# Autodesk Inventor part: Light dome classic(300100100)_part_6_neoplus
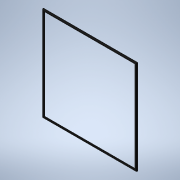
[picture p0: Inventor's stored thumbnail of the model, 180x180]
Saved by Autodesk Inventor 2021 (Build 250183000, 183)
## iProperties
Created: 2026-04
Part Number: Light dome classic(300100100)_part_6_neoplus
Material: Generic
Catalog Web Link: www.3dfindit.com
Description: Light dome classic_part_6_neoplus-
Vendor: KINGSPAN
Document SubType Name: Modeling
Designer: psAdmin
Manufacturer: KINGSPAN
Mass: 667.294 g
Surface Area: 1846.83 cm^2
Volume: 667.294 cm^3
Density: 1 g/cm^3
Appearance: PSOLRGB-128-128-128
Category: PARTsolutions
Company: KINGSPAN
Title: Light dome classic(300100100)_part_6_neoplus
Author: Cadenas PARTsolutions
PSOL_IDENT_0: {$CADENAS_DATA/23d-libs/kingspan_kla/light_dome_classic_neoplus/parts/part_6.prj},268 {VTYP=3D},{NB=
PSOL_IDENT_1: Light dome classic(300100100)_part_6_neoplus},{LINA=Light dome classic(300100100)_part_6_neoplus},{N
PSOL_IDENT_2: N=Light dome classic_part_6_neoplus},{DATE=20.03.2025 09:30:52},{GEOMDATE=27.10.2022 10:10:00},{VERS
PSOL_IDENT_3: ION=},{LINEID=10},{WBVAR=LODLEVEL,L,W},{WBNUMERIC=W}  {NB=Light dome classic(300100100)_part_6_neopl
PSOL_IDENT_4: us},{LINA=Light dome classic(300100100)_part_6_neoplus},{KT=DUMMY},{IDNR=},{PN=Light dome classic},{
PSOL_IDENT_5: LODLEVEL=300},{L=100},{W=100},{WX=100,150,200,250,300},{LX=1000},{XWX=1000}
NB: Light dome classic(300100100)_part_6_neoplus
NN: Light dome classic_part_6_neoplus
NBSYN: $PN.($LODLEVEL.$L.$W.)_part_6_neoplus
LINA: Light dome classic(300100100)_part_6_neoplus
CATALOG: Light + Air
PN: Light dome classic
LODLEVEL: 300
L: 100
W: 100
SUPPLIER: KINGSPAN
ARTICLENO: Light dome classic(300100100)_part_6_neoplus
BOMINFO: Light dome classic(300100100)_part_6_neoplus
CREATOR: CADENAS GmbH
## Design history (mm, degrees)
sketch "Sketch_1"
  geometry: L1 (-423.235, 17.946)-(-433.911, 17.946); L2 (-435.365, 1.946)-(-426.535, 1.946); L3 (-424.735, 12.349)-(-423.235, 17.946); A1 r 12.5 centre (-425.1, 9.079) between (-433.911, 17.946) and (-435.365, 1.946); A2 r 12.5 centre (-436.8, 9.079) between (-426.535, 1.946) and (-424.735, 12.349)
  constraints: 6 end point, 4 point on circle, 2 centre point
extrude "Extrusion1" join sketch "Sketch_1" stored distance "d0" = 2000; taper "d1" = 0 deg
sketch "Sketch_2"
  geometry: L1 (423.235, 17.946)-(424.735, 12.349); L2 (426.535, 1.946)-(435.365, 1.946); L3 (433.911, 17.946)-(423.235, 17.946); A1 r 12.5 centre (436.8, 9.079) between (424.735, 12.349) and (426.535, 1.946); A2 r 12.5 centre (425.1, 9.079) between (435.365, 1.946) and (433.911, 17.946)
  constraints: 6 end point, 4 point on circle, 2 centre point
extrude "Extrusion2" join sketch "Sketch_2" stored distance "d2" = 2000; taper "d3" = 0 deg
sketch "Sketch_3"
  geometry: L1 (433.911, 17.946)-(423.235, 17.946); L2 (423.235, 17.946)-(424.735, 12.349); L3 (426.535, 1.946)-(435.365, 1.946); A1 r 12.5 centre (425.1, 9.079) between (435.365, 1.946) and (433.911, 17.946); A2 r 12.5 centre (436.8, 9.079) between (424.735, 12.349) and (426.535, 1.946)
  constraints: 6 end point, 4 point on circle, 2 centre point
extrude "Extrusion3" join sketch "Sketch_3" stored distance "d4" = 2000; taper "d5" = 0 deg
sketch "Sketch_4"
  geometry: L1 (-423.235, 17.946)-(-433.911, 17.946); L2 (-435.365, 1.946)-(-426.535, 1.946); L3 (-424.735, 12.349)-(-423.235, 17.946); A1 r 12.5 centre (-425.1, 9.079) between (-433.911, 17.946) and (-435.365, 1.946); A2 r 12.5 centre (-436.8, 9.079) between (-426.535, 1.946) and (-424.735, 12.349)
  constraints: 6 end point, 4 point on circle, 2 centre point
extrude "Extrusion4" join sketch "Sketch_4" stored distance "d6" = 2000; taper "d7" = 0 deg
sketch "Sketch_5"
  geometry: L1 (-429.25, 37.946)-(-1000, 37.946); L2 (-1000, 37.946)-(-1000, -12.054); L3 (-1000, -12.054)-(-436.988, -12.054); L4 (-436.988, -12.054)-(-436.988, 5.216); L5 (-433.911, 17.946)-(-429.25, 17.946); L6 (-429.25, 17.946)-(-429.25, 37.946); A1 r 12.5 centre (-425.1, 9.079) between (-433.911, 17.946) and (-436.988, 5.216)
  constraints: 12 end point, 2 point on circle, 1 centre point
extrude "Extrusion5" cut sketch "Sketch_5" stored distance "d8" = 2000; taper "d9" = 0 deg
sketch "Sketch_6"
  geometry: L1 (1000, -12.054)-(1000, 37.946); L2 (1000, 37.946)-(429.25, 37.946); L3 (429.25, 37.946)-(429.25, 17.946); L4 (429.25, 17.946)-(433.911, 17.946); L5 (436.988, 5.216)-(436.988, -12.054); L6 (436.988, -12.054)-(1000, -12.054); A1 r 12.5 centre (425.1, 9.079) between (436.988, 5.216) and (433.911, 17.946)
  constraints: 12 end point, 2 point on circle, 1 centre point
extrude "Extrusion6" cut sketch "Sketch_6" stored distance "d10" = 2000; taper "d11" = 0 deg
sketch "Sketch_7"
  geometry: L1 (1000, 37.946)-(429.25, 37.946); L2 (429.25, 37.946)-(429.25, 17.946); L3 (429.25, 17.946)-(433.911, 17.946); L4 (436.988, 5.216)-(436.988, -12.054); L5 (436.988, -12.054)-(1000, -12.054); L6 (1000, -12.054)-(1000, 37.946); A1 r 12.5 centre (425.1, 9.079) between (436.988, 5.216) and (433.911, 17.946)
  constraints: 12 end point, 2 point on circle, 1 centre point
extrude "Extrusion7" cut sketch "Sketch_7" stored distance "d12" = 2000; taper "d13" = 0 deg
sketch "Sketch_8"
  geometry: L1 (-1000, 37.946)-(-1000, -12.054); L2 (-1000, -12.054)-(-436.988, -12.054); L3 (-436.988, -12.054)-(-436.988, 5.216); L4 (-433.911, 17.946)-(-429.25, 17.946); L5 (-429.25, 17.946)-(-429.25, 37.946); L6 (-429.25, 37.946)-(-1000, 37.946); A1 r 12.5 centre (-425.1, 9.079) between (-433.911, 17.946) and (-436.988, 5.216)
  constraints: 12 end point, 2 point on circle, 1 centre point
extrude "Extrusion8" cut sketch "Sketch_8" stored distance "d14" = 2000; taper "d15" = 0 deg
sketch "Sketch_10"
  geometry: L1 (-430.95, -7.054)-(-430.95, -1.143); L2 (-437.201, 5.946)-(-443.235, 5.946); L3 (-443.235, 5.946)-(-443.235, -7.054); L4 (-443.235, -7.054)-(-430.95, -7.054); A1 r 3.851 centre (-430.95, 2.708) between (-433.505, -0.173) and (-430.95, -1.143); A2 r 12.5 centre (-425.1, 9.079) between (-437.201, 5.946) and (-433.505, -0.173)
  constraints: 8 end point, 4 point on circle, 2 centre point
extrude "Extrusion9" cut sketch "Sketch_10" stored distance "d16" = 1000; taper "d17" = 0 deg
sketch "Sketch_11"
  geometry: L1 (443.235, 5.946)-(437.201, 5.946); L2 (430.95, -1.143)-(430.95, -7.054); L3 (430.95, -7.054)-(443.235, -7.054); L4 (443.235, -7.054)-(443.235, 5.946); A1 r 12.5 centre (425.1, 9.079) between (433.505, -0.173) and (437.201, 5.946); A2 r 3.851 centre (430.95, 2.708) between (430.95, -1.143) and (433.505, -0.173)
  constraints: 8 end point, 4 point on circle, 2 centre point
extrude "Extrusion10" cut sketch "Sketch_11" stored distance "d18" = 1000; taper "d19" = 0 deg
sketch "Sketch_12"
  geometry: L1 (443.235, 5.946)-(437.201, 5.946); L2 (430.95, -1.143)-(430.95, -7.054); L3 (430.95, -7.054)-(443.235, -7.054); L4 (443.235, -7.054)-(443.235, 5.946); A1 r 12.5 centre (425.1, 9.079) between (433.505, -0.173) and (437.201, 5.946); A2 r 3.851 centre (430.95, 2.708) between (430.95, -1.143) and (433.505, -0.173)
  constraints: 8 end point, 4 point on circle, 2 centre point
extrude "Extrusion11" cut sketch "Sketch_12" stored distance "d20" = 1000; taper "d21" = 0 deg
sketch "Sketch_13"
  geometry: L1 (-443.235, 5.946)-(-443.235, -7.054); L2 (-443.235, -7.054)-(-430.95, -7.054); L3 (-430.95, -7.054)-(-430.95, -1.143); L4 (-437.201, 5.946)-(-443.235, 5.946); A1 r 3.851 centre (-430.95, 2.708) between (-433.505, -0.173) and (-430.95, -1.143); A2 r 12.5 centre (-425.1, 9.079) between (-437.201, 5.946) and (-433.505, -0.173)
  constraints: 8 end point, 4 point on circle, 2 centre point
extrude "Extrusion12" cut sketch "Sketch_13" stored distance "d22" = 1000; taper "d23" = 0 deg
node "IP_6_XY"
node "IP_6_YZ"
node "IP_6_ZX"
node "IP_6_X"
node "IP_6_Y"
node "IP_6_Z"
node "IP_6_Center"
body "Solid1"
other parameters: "d24" = 0
